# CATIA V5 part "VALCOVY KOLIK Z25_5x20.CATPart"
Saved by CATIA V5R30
Part number: VALCOVY KOLIK Z25/5x20
Bounding box of the stored display mesh (mm): x -19.992 to 0, y -2.5 to 2.5, z -2.5 to 2.5
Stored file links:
  C:\Users\ondra\Desktop\PŘÍLOHA P III\CATIA\VALCOVY KOLIK Z25_5x20.CATPart
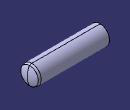
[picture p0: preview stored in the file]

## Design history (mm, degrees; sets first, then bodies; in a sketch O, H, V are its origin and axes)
Set1
  DatumSurface1 to DatumSurface8 "Z25/5x20"
  Join1: Elements (DatumSurface1; DatumSurface2; DatumSurface3; DatumSurface4; DatumSurface5; DatumSurface6; DatumSurface7; DatumSurface8)
Body1 (main body)
  CloseSurface1: CloseElement Join1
